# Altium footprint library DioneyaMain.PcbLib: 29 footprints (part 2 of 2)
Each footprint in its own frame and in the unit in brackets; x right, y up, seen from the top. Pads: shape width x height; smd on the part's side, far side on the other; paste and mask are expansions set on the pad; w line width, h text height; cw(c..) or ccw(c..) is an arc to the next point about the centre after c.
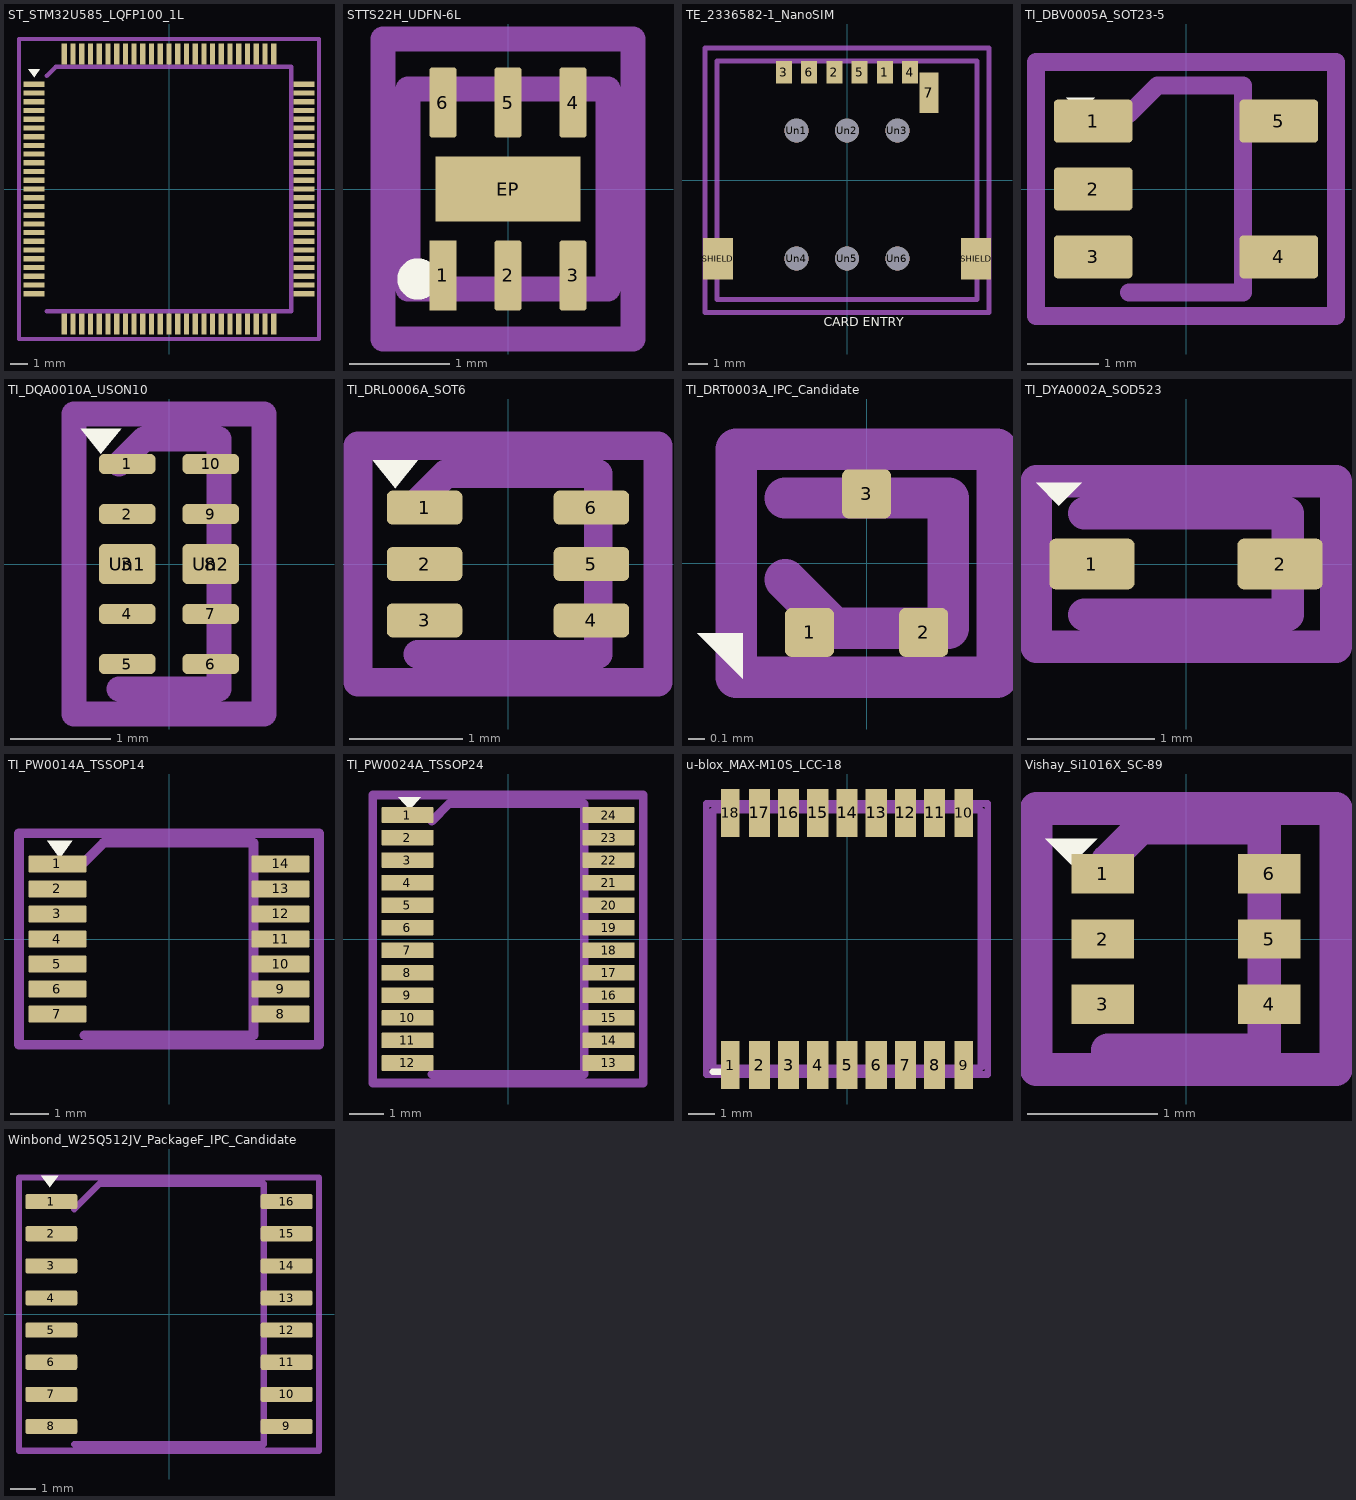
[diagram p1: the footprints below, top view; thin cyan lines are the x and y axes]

## ST_STM32U585_LQFP100_1L [mm]
pads (100):
  rect 1.2x0.3 smd: 1(-7.75,6) 2(-7.75,5.5) 3(-7.75,5) 4(-7.75,4.5) 5(-7.75,4) 6(-7.75,3.5) 7(-7.75,3) 8(-7.75,2.5) 9(-7.75,2) 10(-7.75,1.5) 11(-7.75,1) 12(-7.75,0.5) 13(-7.75,0) 14(-7.75,-0.5) 15(-7.75,-1) 16(-7.75,-1.5) 17(-7.75,-2) 18(-7.75,-2.5) 19(-7.75,-3) 20(-7.75,-3.5) 21(-7.75,-4) 22(-7.75,-4.5) 23(-7.75,-5) 24(-7.75,-5.5) 25(-7.75,-6) 51(7.75,-6) 52(7.75,-5.5) 53(7.75,-5) 54(7.75,-4.5) 55(7.75,-4) 56(7.75,-3.5) 57(7.75,-3) 58(7.75,-2.5) 59(7.75,-2) 60(7.75,-1.5) 61(7.75,-1) 62(7.75,-0.5) 63(7.75,0) 64(7.75,0.5) 65(7.75,1) 66(7.75,1.5) 67(7.75,2) 68(7.75,2.5) 69(7.75,3) 70(7.75,3.5) 71(7.75,4) 72(7.75,4.5) 73(7.75,5) 74(7.75,5.5) 75(7.75,6)
  rect 0.3x1.2 smd: 26(-6,-7.75) 27(-5.5,-7.75) 28(-5,-7.75) 29(-4.5,-7.75) 30(-4,-7.75) 31(-3.5,-7.75) 32(-3,-7.75) 33(-2.5,-7.75) 34(-2,-7.75) 35(-1.5,-7.75) 36(-1,-7.75) 37(-0.5,-7.75) 38(0,-7.75) 39(0.5,-7.75) 40(1,-7.75) 41(1.5,-7.75) 42(2,-7.75) 43(2.5,-7.75) 44(3,-7.75) 45(3.5,-7.75) 46(4,-7.75) 47(4.5,-7.75) 48(5,-7.75) 49(5.5,-7.75) 50(6,-7.75) 76(6,7.75) 77(5.5,7.75) 78(5,7.75) 79(4.5,7.75) 80(4,7.75) 81(3.5,7.75) 82(3,7.75) 83(2.5,7.75) 84(2,7.75) 85(1.5,7.75) 86(1,7.75) 87(0.5,7.75) 88(0,7.75) 89(-0.5,7.75) 90(-1,7.75) 91(-1.5,7.75) 92(-2,7.75) 93(-2.5,7.75) 94(-3,7.75) 95(-3.5,7.75) 96(-4,7.75) 97(-4.5,7.75) 98(-5,7.75) 99(-5.5,7.75) 100(-6,7.75)
F.SilkS:
  region: -7.738,6.41 -8.077,6.88 -7.398,6.88
F.Fab:
  lines w0.254: -7,-7 7,-7 7,7 -6.5,7 -7,6.5
F.CrtYd:
  lines w0.254: -8.6,-8.6 -8.6,8.6 8.6,8.6 8.6,-8.6 -8.6,-8.6

## STTS22H_UDFN-6L [mm]
pads (7):
  rect 0.27x0.7 smd: 1(-0.65,-0.865)
  rrect20% 0.27x0.7 smd: 2(0,-0.865) 3(0.65,-0.865) 4(0.65,0.865) 5(0,0.865) 6(-0.65,0.865)
  rect 1.45x0.65 smd: EP(0,0)
F.SilkS:
  circle w0.254: c-0.9,-0.9 r0.08
F.Fab:
  lines w0.254: -1,-1 -1,1 1,1 1,-1 -1,-1
F.CrtYd:
  lines w0.254: -1.25,-1.5 -1.25,1.5 1.25,1.5 1.25,-1.5 -1.25,-1.5

## TE_2336582-1_NanoSIM [mm]
pads (15):
  rect 0.8x1.14 smd: 1(1.905,5.43) 2(-0.635,5.43) 3(-3.175,5.43) 4(3.175,5.43) 5(0.635,5.43) 6(-1.905,5.43)
  rect 0.95x2.05 smd: 7(4.125,4.405)
  rect 1.5x2.1 smd: SHIELD(-6.5,-3.95) SHIELD(6.5,-3.95)
  round 1.2 hole 1.2: Un1(-2.54,2.5) Un2(0,2.5) Un3(2.54,2.5) Un4(-2.54,-3.94) Un5(0,-3.94) Un6(2.54,-3.94)
F.SilkS:
  text "CARD ENTRY" at -1.172,-7.527 h0.8
F.Fab:
  lines w0.254: -4.2,-6 4.2,-6 ; -6.545,-6 -6.545,6 6.545,6 6.545,-6 -6.545,-6
F.CrtYd:
  lines w0.254: -7.15,-6.65 -7.15,6.65 7.15,6.65 7.15,-6.65 -7.15,-6.65

## TI_DBV0005A_SOT23-5 [mm]
pads (5):
  rrect17% 1.1x0.6 smd: 1(-1.3,0.95) 2(-1.3,0) 3(-1.3,-0.95) 4(1.3,-0.95) 5(1.3,0.95)
F.SilkS:
  region: -1.48,1.08 -1.68,1.28 -1.28,1.28
F.Fab:
  lines w0.254: -0.8,-1.45 0.8,-1.45 0.8,1.45 -0.4,1.45 -0.8,1.05
F.CrtYd:
  lines w0.254: -2.1,-1.78 -2.1,1.78 2.1,1.78 2.1,-1.78 -2.1,-1.78

## TI_DQA0010A_USON10 [mm]
pads (12):
  rrect50% 0.565x0.2 smd: 1(-0.417,1) 2(-0.417,0.5) 4(-0.417,-0.5) 5(-0.417,-1) 6(0.417,-1) 7(0.417,-0.5) 9(0.417,0.5) 10(0.417,1)
  rrect25% 0.565x0.4 smd: 3(-0.417,0) 8(0.417,0)
  rrect28% 0.565x0.36 on Top Paste: Un1(-0.417,0) Un2(0.417,0)
F.SilkS:
  region: -0.68,1.1 -0.88,1.35 -0.48,1.35
F.Fab:
  lines w0.254: -0.5,-1.25 0.5,-1.25 0.5,1.25 -0.25,1.25 -0.5,1
F.CrtYd:
  lines w0.254: -0.95,-1.5 -0.95,1.5 0.95,1.5 0.95,-1.5 -0.95,-1.5

## TI_DRL0006A_SOT6 [mm]
pads (6):
  rrect33% 0.67x0.3 smd: 1(-0.74,0.5) 2(-0.74,0) 3(-0.74,-0.5) 4(0.74,-0.5) 5(0.74,0) 6(0.74,0.5)
F.SilkS:
  region: -1,0.67 -1.2,0.92 -0.8,0.92
F.Fab:
  lines w0.254: -0.8,-0.8 0.8,-0.8 0.8,0.8 -0.55,0.8 -0.8,0.55
F.CrtYd:
  lines w0.254: -1.33,-1.05 -1.33,1.05 1.33,1.05 1.33,-1.05 -1.33,-1.05

## TI_DRT0003A_IPC_Candidate [mm]
pads (3):
  rrect25% 0.3x0.3 smd: 1(-0.35,-0.425) 2(0.35,-0.425) 3(0,0.425)
F.SilkS:
  region: -0.76,-0.71 -1.04,-0.43 -0.76,-0.43
F.Fab:
  lines w0.254: -0.5,-0.1 -0.2,-0.4 0.5,-0.4 0.5,0.4 -0.5,0.4
F.CrtYd:
  lines w0.254: -0.8,-0.7 -0.8,0.7 0.8,0.7 0.8,-0.7 -0.8,-0.7

## TI_DYA0002A_SOD523 [mm]
pads (2):
  rrect25% 0.67x0.4 smd: 1(-0.74,0) 2(0.74,0)
F.SilkS:
  region: -1,0.46 -1.18,0.64 -0.82,0.64
F.Fab:
  lines w0.254: -0.8,-0.4 0.8,-0.4 0.8,0.4 -0.8,0.4
F.CrtYd:
  lines w0.254: -1.18,-0.65 -1.18,0.65 1.18,0.65 1.18,-0.65 -1.18,-0.65

## TI_PW0014A_TSSOP14 [mm]
pads (14):
  rrect11% 1.5x0.45 smd: 1(-2.9,1.95) 2(-2.9,1.3) 3(-2.9,0.65) 4(-2.9,0) 5(-2.9,-0.65) 6(-2.9,-1.3) 7(-2.9,-1.95) 8(2.9,-1.95) 9(2.9,-1.3) 10(2.9,-0.65) 11(2.9,0) 12(2.9,0.65) 13(2.9,1.3) 14(2.9,1.95)
F.SilkS:
  region: -2.84,2.1 -3.16,2.55 -2.52,2.55
F.Fab:
  lines w0.254: -2.2,-2.5 2.2,-2.5 2.2,2.5 -1.7,2.5 -2.2,2
F.CrtYd:
  lines w0.254: -3.9,-2.75 -3.9,2.75 3.9,2.75 3.9,-2.75 -3.9,-2.75

## TI_PW0024A_TSSOP24 [mm]
pads (24):
  rrect11% 1.5x0.45 smd: 1(-2.9,3.575) 2(-2.9,2.925) 3(-2.9,2.275) 4(-2.9,1.625) 5(-2.9,0.975) 6(-2.9,0.325) 7(-2.9,-0.325) 8(-2.9,-0.975) 9(-2.9,-1.625) 10(-2.9,-2.275) 11(-2.9,-2.925) 12(-2.9,-3.575) 13(2.9,-3.575) 14(2.9,-2.925) 15(2.9,-2.275) 16(2.9,-1.625) 17(2.9,-0.975) 18(2.9,-0.325) 19(2.9,0.325) 20(2.9,0.975) 21(2.9,1.625) 22(2.9,2.275) 23(2.9,2.925) 24(2.9,3.575)
F.SilkS:
  region: -2.84,3.73 -3.16,4.08 -2.52,4.08
F.Fab:
  lines w0.254: -2.2,-3.9 2.2,-3.9 2.2,3.9 -1.7,3.9 -2.2,3.4
F.CrtYd:
  lines w0.254: -3.9,-4.15 -3.9,4.15 3.9,4.15 3.9,-4.15 -3.9,-4.15

## u-blox_MAX-M10S_LCC-18 [mm]
pads (18):
  rect 0.7x1.8 smd: 1(-4.4,-4.75) 9(4.4,-4.75) 10(4.4,4.75) 18(-4.4,4.75)
  rect 0.8x1.8 smd: 2(-3.3,-4.75) 3(-2.2,-4.75) 4(-1.1,-4.75) 5(0,-4.75) 6(1.1,-4.75) 7(2.2,-4.75) 8(3.3,-4.75) 11(3.3,4.75) 12(2.2,4.75) 13(1.1,4.75) 14(0,4.75) 15(-1.1,4.75) 16(-2.2,4.75) 17(-3.3,4.75)
F.SilkS:
  lines w0.254: -5.05,-5 -4.55,-5
F.Fab:
  lines w0.254: -5.05,-4.85 -5.05,4.85 5.05,4.85 5.05,-4.85 -5.05,-4.85
F.CrtYd:
  lines w0.254: -5.3,-5.1 -5.3,5.1 5.3,5.1 5.3,-5.1 -5.3,-5.1

## Vishay_Si1016X_SC-89 [mm]
pads (6):
  rect 0.478x0.3 smd: 1(-0.638,0.5) 2(-0.638,0) 3(-0.638,-0.5) 4(0.638,-0.5) 5(0.638,0) 6(0.638,0.5)
F.SilkS:
  region: -0.88,0.57 -1.08,0.77 -0.68,0.77
F.Fab:
  lines w0.254: -0.6,-0.85 0.6,-0.85 0.6,0.85 -0.35,0.85 -0.6,0.6
F.CrtYd:
  lines w0.254: -1.15,-1 -1.15,1 1.15,1 1.15,-1 -1.15,-1

## Winbond_W25Q512JV_PackageF_IPC_Candidate [mm]
pads (16):
  rrect25% 2.05x0.6 smd: 1(-4.65,4.445) 2(-4.65,3.175) 3(-4.65,1.905) 4(-4.65,0.635) 5(-4.65,-0.635) 6(-4.65,-1.905) 7(-4.65,-3.175) 8(-4.65,-4.445) 9(4.65,-4.445) 10(4.65,-3.175) 11(4.65,-1.905) 12(4.65,-0.635) 13(4.65,0.635) 14(4.65,1.905) 15(4.65,3.175) 16(4.65,4.445)
F.SilkS:
  region: -4.713,5.005 -5.052,5.475 -4.373,5.475
F.Fab:
  lines w0.254: -3.75,-5.15 3.75,-5.15 3.75,5.15 -2.75,5.15 -3.75,4.15
F.CrtYd:
  lines w0.254: -5.93,-5.4 -5.93,5.4 5.93,5.4 5.93,-5.4 -5.93,-5.4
